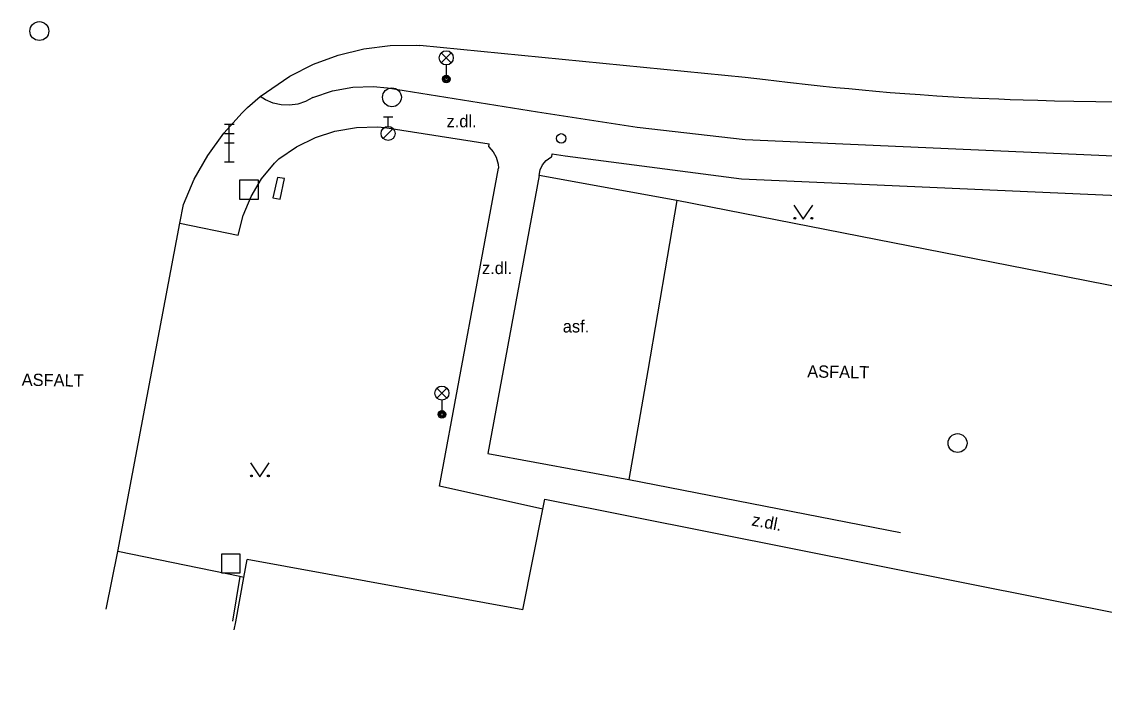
# Model space of a CAD drawing. Extents: x -538441 to -536770, y -1181008 to -1179809.
# Drawn here: x -537570.7 to -537513.4, y -1180925.8 to -1180890.8 of the extents above; entities that cross this region are included whole.
import ezdxf

# ---------------------------------------------------------------- set-up
doc = ezdxf.new("R2010")
doc.units = 0
for name, color, linetype in [('Vrstva 10', 7, 'Continuous'), ('Vrstva 11', 7, 'Continuous'), ('Vrstva 26', 7, 'Continuous'), ('Vrstva 27', 7, 'Continuous'), ('Vrstva 28', 7, 'Continuous'), ('Vrstva 30', 7, 'Continuous'), ('Vrstva 33', 7, 'Continuous'), ('Vrstva 36', 7, 'Continuous'), ('Vrstva 40', 7, 'Continuous'), ('Vrstva 5', 7, 'Continuous')]:
    doc.layers.add(name, color=color, linetype=linetype)

msp = doc.modelspace()

# ---------------------------------------------------------------- linework, layer by layer
at = {"layer": 'Vrstva 10'}
for p, q in [((-537532.405, -1180893.792), (-537549.621, -1180892.094)), ((-537543.31, -1180898.99), (-537546.03, -1180913.72)), ((-537536.017, -1180900.307), (-537543.31, -1180898.99)), ((-537562.348, -1180901.521), (-537562.145, -1180900.522)), ((-537536.017, -1180900.307), (-537537.546, -1180909.328)), ((-537517.552, -1180903.941), (-537536.017, -1180900.307)), ((-537565.623, -1180918.918), (-537562.348, -1180901.521)), ((-537506.303, -1180906.138), (-537517.552, -1180903.941)), ((-537537.546, -1180909.328), (-537538.564, -1180915.101)), ((-537546.03, -1180913.72), (-537538.564, -1180915.101)), ((-537538.564, -1180915.101), (-537524.175, -1180917.904)), ((-537566.242, -1180921.971), (-537565.623, -1180918.918))]:
    msp.add_line(p, q, dxfattribs=at)
for points in [[(-537558.751, -1180895.391), (-537558.08, -1180894.8), (-537556.509, -1180893.723), (-537555.261, -1180893.092), (-537553.948, -1180892.607), (-537552.589, -1180892.275), (-537551.2, -1180892.1), (-537549.801, -1180892.084), (-537549.621, -1180892.094)], [(-537523.13, -1180894.72), (-537523.936, -1180894.66), (-537524.716, -1180894.598), (-537525.471, -1180894.533), (-537526.202, -1180894.467), (-537526.91, -1180894.4), (-537527.595, -1180894.333), (-537528.259, -1180894.265), (-537528.902, -1180894.197), (-537530.146, -1180894.059), (-537531.312, -1180893.924), (-537532.405, -1180893.792)], [(-537512.501, -1180895.109), (-537513.83, -1180895.088), (-537514.993, -1180895.066), (-537516.01, -1180895.042), (-537516.901, -1180895.019), (-537517.68, -1180894.995), (-537518.361, -1180894.971), (-537518.957, -1180894.948), (-537520.001, -1180894.903), (-537520.783, -1180894.864), (-537521.37, -1180894.833), (-537522.25, -1180894.779), (-537523.13, -1180894.72)], [(-537562.145, -1180900.522), (-537561.575, -1180899.188), (-537560.862, -1180897.925), (-537560.014, -1180896.747), (-537559.042, -1180895.671), (-537558.751, -1180895.391)], [(-537557.033, -1180900.248), (-537556.799, -1180899.154), (-537557.176, -1180899.087), (-537557.407, -1180900.168), (-537557.033, -1180900.248)]]:
    msp.add_lwpolyline(points, dxfattribs=at)
at = {"layer": 'Vrstva 11'}
for p, q in [((-537551.347, -1180894.334), (-537543.395, -1180895.616)), ((-537543.395, -1180895.616), (-537538.11, -1180896.43)), ((-537551.481, -1180896.435), (-537545.955, -1180897.309)), ((-537538.11, -1180896.43), (-537532.399, -1180897.076)), ((-537532.399, -1180897.076), (-537509.338, -1180898.108)), ((-537545.98, -1180897.46), (-537545.955, -1180897.309)), ((-537542.64, -1180898), (-537542.614, -1180897.839)), ((-537542.614, -1180897.839), (-537541.927, -1180897.948)), ((-537541.927, -1180897.948), (-537532.593, -1180899.158)), ((-537548.58, -1180915.45), (-537545.47, -1180898.6)), ((-537532.593, -1180899.158), (-537512.251, -1180900.066)), ((-537562.348, -1180901.521), (-537559.251, -1180902.157)), ((-537543.115, -1180916.669), (-537548.58, -1180915.45)), ((-537559.17, -1180920.25), (-537559.55, -1180922.61))]:
    msp.add_line(p, q, dxfattribs=at)
for points in [[(-537555.297, -1180894.852), (-537554.262, -1180894.501), (-537553.186, -1180894.305), (-537552.094, -1180894.267), (-537551.347, -1180894.334)], [(-537555.297, -1180894.852), (-537555.681, -1180895.064), (-537556.097, -1180895.204), (-537556.532, -1180895.265), (-537556.971, -1180895.247), (-537557.399, -1180895.15), (-537557.802, -1180894.976), (-537558.08, -1180894.8)], [(-537557.093, -1180898.099), (-537556.167, -1180897.468), (-537555.16, -1180896.974), (-537554.124, -1180896.637), (-537552.988, -1180896.439), (-537551.868, -1180896.409), (-537551.481, -1180896.435)], [(-537545.98, -1180897.46), (-537545.747, -1180897.729), (-537545.59, -1180898.02), (-537545.488, -1180898.387), (-537545.47, -1180898.6)], [(-537559.251, -1180902.157), (-537558.987, -1180901.103), (-537558.57, -1180900.1), (-537558.011, -1180899.168), (-537557.322, -1180898.329), (-537557.093, -1180898.099)], [(-537543.31, -1180898.99), (-537543.259, -1180898.694), (-537543.13, -1180898.42), (-537542.937, -1180898.193), (-537542.689, -1180898.024), (-537542.64, -1180898)], [(-537558.953, -1180920.297), (-537559.17, -1180920.25), (-537565.623, -1180918.918)]]:
    msp.add_lwpolyline(points, dxfattribs=at)
at = {"layer": 'Vrstva 26'}
for points in [[(-537559.18, -1180900.24), (-537558.18, -1180900.24), (-537558.18, -1180899.24), (-537559.18, -1180899.24)], [(-537560.141, -1180920.056), (-537559.141, -1180920.056), (-537559.141, -1180919.056), (-537560.141, -1180919.056)]]:
    msp.add_lwpolyline(points, close=True, dxfattribs=at)
at = {"layer": 'Vrstva 27'}
for centre in [(-537569.784, -1180891.332), (-537521.146, -1180913.171)]:
    msp.add_circle(centre, 0.5, dxfattribs=at)
at = {"layer": 'Vrstva 28'}
for p, q in [((-537551.56, -1180895.885), (-537551.06, -1180895.885)), ((-537551.31, -1180896.385), (-537551.31, -1180895.885)), ((-537551.568, -1180897.032), (-537551.038, -1180896.502))]:
    msp.add_line(p, q, dxfattribs=at)
for centre, radius in [((-537551.31, -1180896.76), 0.375), ((-537542.14, -1180897.02), 0.25)]:
    msp.add_circle(centre, radius, dxfattribs=at)
at = {"layer": 'Vrstva 30'}
msp.add_circle((-537551.106, -1180894.844), 0.5, dxfattribs=at)
at = {"layer": 'Vrstva 33'}
for p, q in [((-537548.495, -1180893.015), (-537547.965, -1180892.485)), ((-537548.495, -1180892.485), (-537547.965, -1180893.015)), ((-537548.23, -1180893.125), (-537548.23, -1180893.875)), ((-537559.971, -1180896.264), (-537559.471, -1180896.264)), ((-537559.721, -1180898.264), (-537559.721, -1180896.264)), ((-537559.971, -1180896.764), (-537559.471, -1180896.764)), ((-537559.971, -1180897.264), (-537559.471, -1180897.264)), ((-537559.971, -1180898.264), (-537559.471, -1180898.264)), ((-537548.725, -1180910.79), (-537548.195, -1180910.26)), ((-537548.725, -1180910.26), (-537548.195, -1180910.79)), ((-537548.46, -1180910.9), (-537548.46, -1180911.65))]:
    msp.add_line(p, q, dxfattribs=at)
for centre, radius in [((-537548.23, -1180892.75), 0.375), ((-537548.23, -1180893.875), 0.2), ((-537548.23, -1180893.875), 0.145), ((-537548.23, -1180893.875), 0.0876), ((-537548.46, -1180910.525), 0.375), ((-537548.46, -1180911.65), 0.2), ((-537548.46, -1180911.65), 0.145), ((-537548.46, -1180911.65), 0.0876)]:
    msp.add_circle(centre, radius, dxfattribs=at)
at = {"layer": 'Vrstva 36'}
for points in [[(-537529.816, -1180900.557), (-537529.316, -1180901.307), (-537528.816, -1180900.557)], [(-537558.603, -1180914.215), (-537558.103, -1180914.965), (-537557.603, -1180914.215)]]:
    msp.add_lwpolyline(points, dxfattribs=at)
for centre in [(-537529.766, -1180901.257), (-537528.867, -1180901.257), (-537558.553, -1180914.915), (-537557.654, -1180914.915)]:
    msp.add_circle(centre, 0.05, dxfattribs=at)
at = {"layer": 'Vrstva 5'}
for p, q in [((-537543.01, -1180916.14), (-537494.84, -1180925.75)), ((-537544.181, -1180922.012), (-537558.78, -1180919.35))]:
    msp.add_line(p, q, dxfattribs=at)
for points in [[(-537544.181, -1180922.012), (-537543.115, -1180916.669), (-537543.01, -1180916.14)], [(-537559.46, -1180923.08), (-537559.38, -1180922.641), (-537558.953, -1180920.297), (-537558.78, -1180919.35)]]:
    msp.add_lwpolyline(points, dxfattribs=at)

# ---------------------------------------------------------------- texts
at = {"layer": 'Vrstva 40'}
for s, p in [('z.dl.', (-537548.215, -1180896.433)), ('z.dl.', (-537546.338, -1180904.214)), ('asf.', (-537542.057, -1180907.31))]:
    msp.add_text(s, height=0.65, dxfattribs=at).set_placement(p)
for s, rotation, p in [('ASFALT', 359.03939, (-537529.114, -1180909.693)), ('ASFALT', 359.03939, (-537570.722, -1180910.131)), ('z.dl.', 348.97674, (-537532.086, -1180917.534))]:
    msp.add_text(s, height=0.65, rotation=rotation, dxfattribs=at).set_placement(p)

doc.saveas('drawing.dxf')
